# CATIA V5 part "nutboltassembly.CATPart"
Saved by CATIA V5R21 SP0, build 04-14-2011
Part number: flange
Bounding box of the stored display mesh (mm): x -150 to 0, y -109.934 to 110, z -109.969 to 109.969
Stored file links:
  F:\catia_prac\nutboltassembly.CATPart
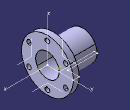
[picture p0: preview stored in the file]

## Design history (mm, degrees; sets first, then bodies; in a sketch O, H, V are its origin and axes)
AxisSystem1: origin (0, 0, 0), X (1, 0, 0), Y (0, 1, 0), Z (0, 0, 1)
Body1 (main body)
  Sketch1 on XY plane of AxisSystem1, origin (0, 0, 0), H (1, 0, 0), V (0, 1, 0)
    line L1 (-150, 50) -> (0, 50)
    point P2 (0, 50)
    line L2 (0, 50) -> (0, 110)
    line L3 (0, 110) -> (-25, 110)
    line L4 (-25, 110) -> (-25, 62)
    line L5 (-25, 62) -> (-150, 62)
    line L6 (-150, 62) -> (-150, 50)
    reference intersected line E1 through (0, 0) direction (-1, 0) from ZX plane of AxisSystem1
    reference intersected line E2 through (0, 0) direction (-1, 0) from ZX plane of AxisSystem1
    length L3 = 25
    length L1 = 150
    distance L3 H = 110
    distance L5 E1 = 62
    distance L1 E2 = 50
    coincidence: P2 V
    horizontal: L1 H, L3 H, L5 H
    vertical: L2 V, L4 V, L6 V
  Shaft1: profile Sketch1, axis edge [XY plane of AxisSystem1 | ZX plane of AxisSystem1], angle 360
  Sketch2 on face of Shaft1 from Sketch1.L4, origin (-25, 0, 0), H (0, -1, 0), V (0, 0, 1)
    circle A1 centre (0, 90) radius 10
    point P1 (0, 90)
    radius A1 = 10
    distance H P1 = 90
    coincidence: P1 V
  Pocket1: profile Sketch2, direction (1, 0, 0), through (limit type 3)
  CircPattern1: of Pocket1, instances 6, angular step 60, axis from edge [XY plane of AxisSystem1 | ZX plane of AxisSystem1]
